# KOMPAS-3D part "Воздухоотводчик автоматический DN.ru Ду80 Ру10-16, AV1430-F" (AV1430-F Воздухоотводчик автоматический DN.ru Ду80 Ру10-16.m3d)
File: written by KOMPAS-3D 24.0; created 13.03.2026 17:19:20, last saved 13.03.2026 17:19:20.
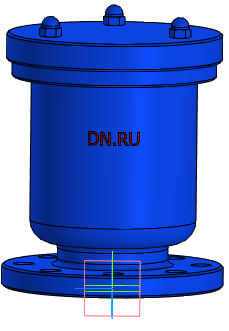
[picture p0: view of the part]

Document properties: Автор: R2D2; Полное имя файла: E:\Работа\Зайцев\AV1430-F Воздухоотводчик автоматический DN.ru Ру10-16 (1)\AV1430-F Воздухоотводчик автоматический DN.ru Ру10-16\DN80\AV1430-F Воздухоотводчик автоматический DN.ru Ду80 Ру10-16.m3d

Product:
- Part/product: Воздухоотводчик автоматический DN.ru Ду80 Ру10-16  | designation AV1430-F
    Масса: 12.5
    Раздел спецификации: Прочие изделия
    Примечание: D030-00255

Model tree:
1. Операция без истории:1

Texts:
  AV1430-F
